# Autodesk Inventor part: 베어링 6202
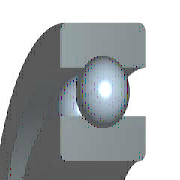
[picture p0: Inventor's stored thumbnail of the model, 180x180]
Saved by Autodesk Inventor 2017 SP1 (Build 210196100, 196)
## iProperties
IsCustomPart: 1
Created: 2015-12
Part Number: 베어링 6202
Material: 강철, 연강
Description: 깊은 그루브 볼 베어링
Document SubType Name: Modeling
Standard: KS B 2023
Designer: mdu
Standards Organization: KS
Language: ko-KR
Size Designation: 6202 - 15 x 35 x 11
Categories: <MemberInstance><Categories><Category DisplayName="샤프트 부품" InternalName="7f7aeb1f-a693-4053-b835-cee3144e0d98" Mnemonic="SHFT"><Category DisplayName="베어링" Inter
Density: 7.86 g/cm^3
Mass: 45.8724 g
Surface Area: 51.5584 cm^2
Volume: 5.83618 cm^3
Appearance: 노란색
Author: mdu
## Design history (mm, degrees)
sketch "스케치" dims "d0" = 5.2 (= -0.26 x WD + 0.26 x BD)
  geometry: L1 (2.9, 12.5)-(8.1, 12.5); L2 (5.5, 12.5)-(5.5, 9.9); L3 (5.5, 12.5)-(5.5, 15.1); L4 (3.568, 10.76)-(0, 10.76); L5 (0, 7.5)-(11, 7.5); L6 (3.568, 14.24)-(0, 14.24); L7 (0, 17.5)-(11, 17.5); L8 (11, 7.5)-(11, 10.76); L9 (7.432, 10.76)-(11, 10.76); L10 (7.432, 14.24)-(11, 14.24); L11 (11, 17.5)-(11, 14.24); L12 (-1.4, 0)-(8.4, 0) reference; L13 (0, -0.3)-(0, 5.3) reference
  constraints: 22 end point, 4 point on line, 2 collinear, 2 perpendicular, 2 symmetric about line, 1 midpoint, 1 parallel, 14 other
  dimensions: "d9" = 15 diameter of L5 L12 (= WD); "d11" = 35 diameter of L7 L12 (= BD); "d12" = 11 distance between parallel lines of L8 L13 (= KB); "d13" = 21.52 diameter of L9 L12 (= 0.326 x BD + 0.674 x WD)
revolve "본체" stored, may be unused: angle "d6" = 90 deg
revolve "볼" stored, may be unused: angle "d7" = 90 deg
pattern_circular "IDS_ARRAYBALL[SIMPL:T]" dims angle "d3" = 360 deg
body "Solid1"
fillet "모깎기1" dims "d1" = 0.6 (= KRS)
other parameters: "WD" = 15 [user parameter; used in 5 equation terms], "BD" = 35 [user parameter; used in 5 equation terms], "KB" = 11 [user parameter; used in 1 equation term], "KRS" = 0.6 [user parameter; used in 1 equation term], "d4" = 0, "d5" = 0, "d8" = 0, "d14" = 0, "d15" = 0, "BBA" = 0 [user parameter], "BC0" = 3750000 [user parameter], "BC" = 7800000 [user parameter], "BR" = 17.5 (= 0.5 x BD) [user parameter], "WR" = 7.5 (= 0.5 x WD) [user parameter]
